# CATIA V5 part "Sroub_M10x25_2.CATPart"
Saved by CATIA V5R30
Part number: Sroub_M10x25_2
Definition: E 1200_10x25_1
Nomenclature: E 1200_10x25_1
Source: Unknown
Description: PART--DESC
Bounding box of the stored display mesh (mm): x -163 to -147, y 82 to 98, z -219 to -184
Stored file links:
  E:\Bakalarka\Model\Forma_v7\Sroub_M10x25_2.CATPart
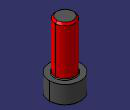
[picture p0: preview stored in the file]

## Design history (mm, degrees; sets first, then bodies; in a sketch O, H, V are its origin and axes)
Body1 "MANIFOLD_SOLID_BREP #4010" (main body)
  Solid1: solid without history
